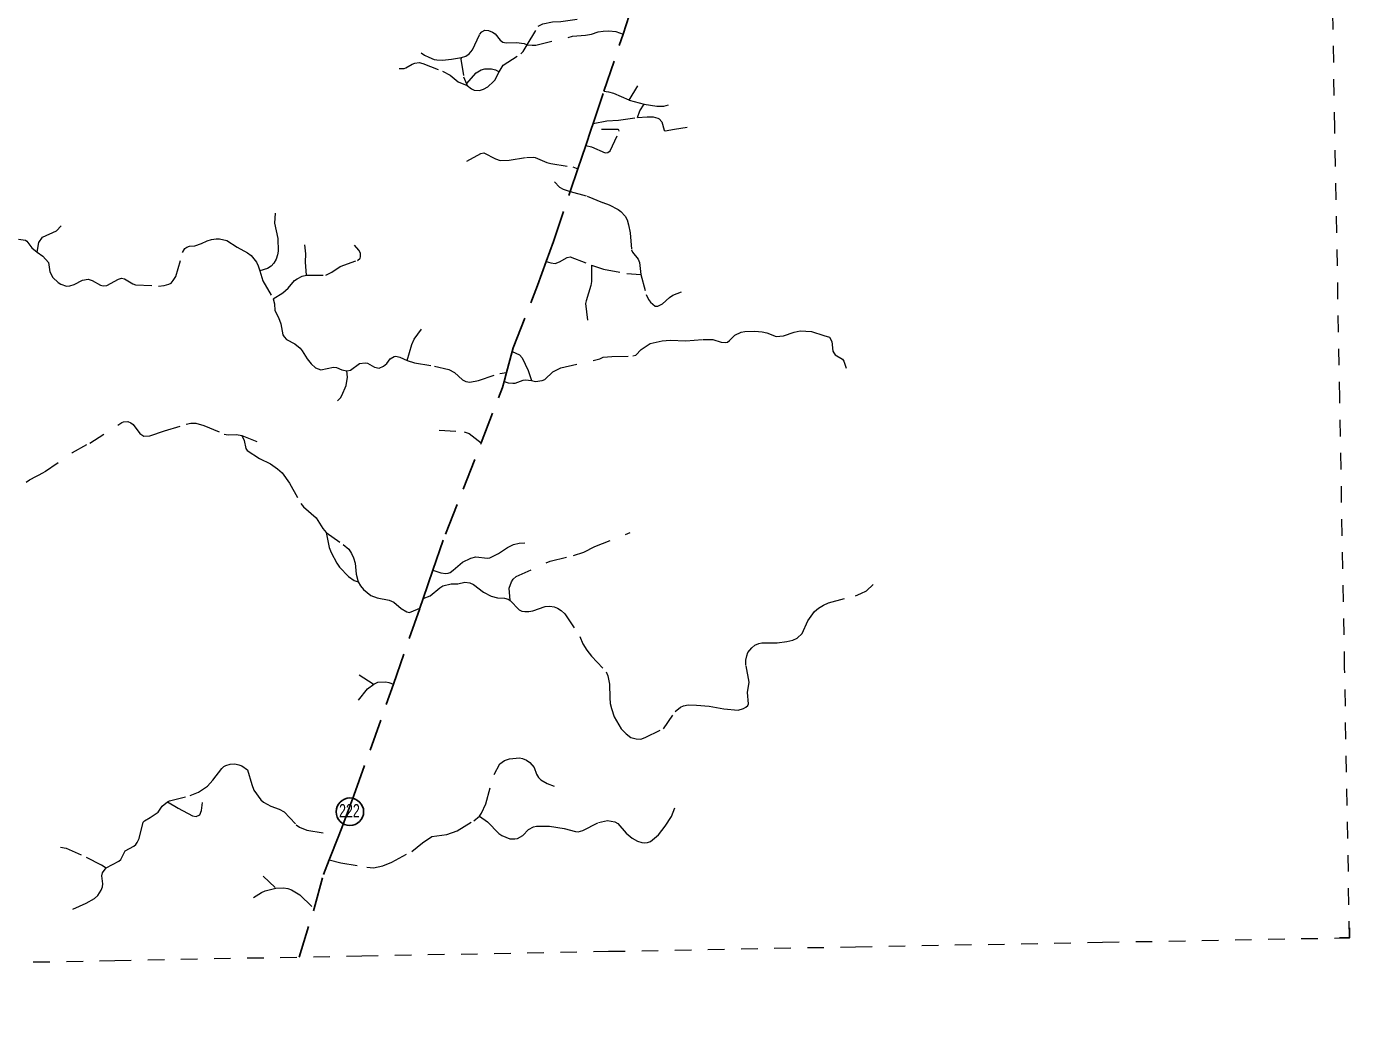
# Model space of a CAD drawing. Extents: x 220.8 to 246.7, y 7287.6 to 7315.8.
# Drawn here: x 238.66 to 246.65, y 7287.6 to 7293.59 of the extents above; entities that cross this region are included whole.
import ezdxf
from ezdxf.enums import TextEntityAlignment as Align

# ---------------------------------------------------------------- set-up
doc = ezdxf.new("R2010")
doc.units = 0
doc.header["$LTSCALE"] = 0.032
for name, pattern in [('DOTTED', [1.5, 0.3, -1.2]), ('LONG_DASHED', [7.5, 6, -1.5]), ('MEDIUM_DASHED', [4.5, 3, -1.5]), ('SHORT_DASHED', [2.7, 1.5, -1.2])]:
    doc.linetypes.add(name, pattern=pattern)
for name, color, linetype, lineweight in [('13', 7, 'Continuous', 25), ('35', 7, 'SHORT_DASHED', 13), ('4', 7, 'LONG_DASHED', 25), ('6', 7, 'MEDIUM_DASHED', 13), ('63', 7, 'Continuous', 25), ('7', 7, 'DOTTED', 13)]:
    doc.layers.add(name, color=color, linetype=linetype, lineweight=lineweight)
doc.layers.add('61', color=7, linetype='Continuous')

msp = doc.modelspace()

# ---------------------------------------------------------------- linework, layer by layer
at = {"layer": '13'}
msp.add_circle((240.6156, 7288.8468), 0.083, dxfattribs=at)
at = {"layer": '35'}
for points in [[(246.6507, 7288.0853), (246.6212, 7289.7146), (246.5917, 7291.3439), (246.5622, 7292.9732), (246.5328, 7294.6024), (246.5034, 7296.2317), (246.4739, 7297.861), (246.4446, 7299.4903), (246.4152, 7301.1196), (246.3858, 7302.7489), (246.3565, 7304.3782), (246.3272, 7306.0075), (246.2979, 7307.6367), (246.2685, 7309.266), (246.2393, 7310.8953), (246.21, 7312.5246), (246.1808, 7314.1539), (246.1516, 7315.7832)], [(221.3035, 7287.6034), (222.7945, 7287.633), (224.2855, 7287.6625), (225.7765, 7287.6918), (227.2675, 7287.7209), (228.7585, 7287.7499), (230.2495, 7287.7787), (231.7405, 7287.8074), (233.2315, 7287.836), (234.7225, 7287.8643), (236.2135, 7287.8925), (237.7045, 7287.9205), (239.1956, 7287.9483), (240.6866, 7287.9761), (242.1776, 7288.0036), (243.6686, 7288.031), (245.1597, 7288.0583), (246.6507, 7288.0853)]]:
    msp.add_lwpolyline(points, dxfattribs=at)
at = {"layer": '4'}
msp.add_lwpolyline([(240.3098, 7287.9691), (240.3989, 7288.2619), (240.4555, 7288.4673), (240.4904, 7288.5558), (240.5484, 7288.7025), (240.5735, 7288.766), (240.64, 7288.9443), (240.8785, 7289.6165), (241.0378, 7290.0769), (241.0582, 7290.1359), (241.1167, 7290.3055), (241.1922, 7290.5244), (241.409, 7291.0743), (241.5361, 7291.4105), (241.546, 7291.4468), (241.5606, 7291.4999), (241.5954, 7291.6273), (241.6014, 7291.649), (241.7482, 7292.0255), (241.8011, 7292.1711), (241.8449, 7292.2916), (241.9456, 7292.5928), (241.9918, 7292.7308), (242.0391, 7292.8714), (242.0721, 7292.9693), (242.084, 7293.0046), (242.1495, 7293.1993), (242.2645, 7293.5438), (242.3022, 7293.6576)], dxfattribs=at)
at = {"layer": '6'}
msp.add_line((239.9637, 7291.1189), (240.054, 7291.0825), dxfattribs=at)
for points in [[(241.7112, 7291.4509), (241.7368, 7291.4466), (241.776, 7291.452), (241.7921, 7291.4589), (241.8404, 7291.5034), (241.8887, 7291.5279), (242.125, 7291.5832), (242.1449, 7291.5924), (242.1963, 7291.5977), (242.3244, 7291.6), (242.3413, 7291.6039), (242.375, 7291.6384), (242.4279, 7291.6744), (242.5, 7291.6921), (242.5491, 7291.6951), (242.6442, 7291.6913), (242.7485, 7291.7005), (242.7884, 7291.7005), (242.8068, 7291.6997), (242.8575, 7291.6829), (242.8812, 7291.6821), (242.8943, 7291.6844), (242.9081, 7291.6944), (242.9403, 7291.7266), (242.9787, 7291.7442), (242.9994, 7291.7488), (243.0607, 7291.7504), (243.1052, 7291.745), (243.1336, 7291.7404), (243.1888, 7291.7182), (243.2341, 7291.7212), (243.2985, 7291.7442), (243.3338, 7291.7519), (243.4028, 7291.7488), (243.4772, 7291.7228), (243.5117, 7291.7143), (243.5255, 7291.6875), (243.5317, 7291.6299), (243.5363, 7291.6192), (243.5462, 7291.6062), (243.5892, 7291.5809), (243.5976, 7291.5694), (243.6122, 7291.5272)], [(241.5954, 7291.6273), (241.6386, 7291.6059), (241.6546, 7291.589), (241.6913, 7291.5127), (241.7112, 7291.4509)], [(241.546, 7291.4468), (241.5712, 7291.4382), (241.5988, 7291.4359), (241.6141, 7291.4367), (241.6609, 7291.4535), (241.6762, 7291.4551), (241.7112, 7291.4509)], [(238.6614, 7290.838), (238.6812, 7290.8522), (238.7716, 7290.9), (238.9406, 7291.0159), (239.0461, 7291.0742), (239.2382, 7291.1976), (239.2494, 7291.2014), (239.2741, 7291.2043), (239.2921, 7291.1969), (239.307, 7291.1857), (239.3481, 7291.1326), (239.3721, 7291.1146), (239.4072, 7291.1184), (239.4954, 7291.1483), (239.6263, 7291.1871), (239.6562, 7291.1939), (239.6861, 7291.1946), (239.7332, 7291.1797), (239.8566, 7291.1281), (239.8813, 7291.1243), (239.9306, 7291.1251), (239.9637, 7291.1189)], [(239.9637, 7291.1189), (239.9777, 7291.0899), (239.9874, 7291.0406), (239.9957, 7291.0286), (240.0704, 7290.9815), (240.1362, 7290.9494), (240.1788, 7290.9187), (240.2065, 7290.8933), (240.2506, 7290.832), (240.3194, 7290.7086), (240.3359, 7290.6884), (240.4114, 7290.6219), (240.4518, 7290.5568), (240.4727, 7290.5334), (240.5751, 7290.4619), (240.6095, 7290.432), (240.626, 7290.4073), (240.6379, 7290.3796), (240.6469, 7290.3475), (240.6529, 7290.2824), (240.6656, 7290.2361), (240.6798, 7290.2121), (240.6978, 7290.1897), (240.7426, 7290.1538), (240.7808, 7290.1396), (240.8518, 7290.1239), (240.881, 7290.1119), (240.9251, 7290.0753), (240.9602, 7290.0544), (240.9729, 7290.0506), (240.9856, 7290.0536), (241.0378, 7290.0769)], [(241.5825, 7290.1221), (241.5775, 7290.1972), (241.5903, 7290.2358), (241.6007, 7290.2526), (241.619, 7290.2669), (241.8253, 7290.3614), (241.9663, 7290.3946), (242.0281, 7290.4143), (242.0939, 7290.4499), (242.308, 7290.533)], [(241.0582, 7290.1359), (241.101, 7290.1517), (241.1587, 7290.2003), (241.1762, 7290.211), (241.2271, 7290.2231), (241.2666, 7290.2239), (241.3091, 7290.2338), (241.3395, 7290.23), (241.3608, 7290.2193), (241.4223, 7290.1722), (241.4678, 7290.1487), (241.5058, 7290.1388), (241.5499, 7290.1366), (241.5704, 7290.1305), (241.5825, 7290.1221)], [(241.5825, 7290.1221), (241.638, 7290.0674), (241.6539, 7290.0591), (241.6721, 7290.056), (241.6957, 7290.0568), (241.7192, 7290.0614), (241.7944, 7290.0864), (241.8225, 7290.0879), (241.8483, 7290.0841), (241.8696, 7290.0766), (241.8916, 7290.0629), (241.9137, 7290.0416), (242.004, 7289.9057), (242.0215, 7289.8601), (242.0458, 7289.8221), (242.0747, 7289.7864), (242.162, 7289.6923), (242.1719, 7289.6672), (242.1833, 7289.6171), (242.1848, 7289.535), (242.1878, 7289.5001), (242.1947, 7289.4713), (242.2106, 7289.4196), (242.2539, 7289.3467), (242.2828, 7289.3171), (242.3124, 7289.2943), (242.3443, 7289.2867), (242.3716, 7289.2859), (242.3982, 7289.2951), (242.5083, 7289.3482), (242.579, 7289.4523), (242.6109, 7289.4788), (242.6298, 7289.4864), (242.6572, 7289.4925), (242.7088, 7289.491), (242.7855, 7289.4849), (242.8729, 7289.4675), (242.9587, 7289.4606), (242.9921, 7289.4697), (243.0065, 7289.4781), (243.0172, 7289.4887), (243.0217, 7289.4994), (243.0157, 7289.5669), (243.0255, 7289.63), (243.0065, 7289.7318), (243.0065, 7289.7629), (243.0111, 7289.7887), (243.0187, 7289.8092), (243.0415, 7289.8373), (243.0597, 7289.8525), (243.0848, 7289.8639), (243.1022, 7289.8677), (243.1949, 7289.8677), (243.2541, 7289.8745), (243.2906, 7289.8836), (243.3149, 7289.8943), (243.346, 7289.9231), (243.3802, 7289.9998), (243.4212, 7290.056), (243.4448, 7290.0766), (243.4744, 7290.0955), (243.5048, 7290.1085), (243.6673, 7290.1517), (243.7007, 7290.1647), (243.7341, 7290.1821), (243.7744, 7290.2186)], [(238.9425, 7288.2584), (239.0241, 7288.2936), (239.0729, 7288.3221), (239.0934, 7288.3406), (239.1138, 7288.3728), (239.1218, 7288.3926), (239.1237, 7288.4117), (239.1181, 7288.46), (239.1224, 7288.4779), (239.1434, 7288.507), (239.2207, 7288.5478), (239.2331, 7288.5589), (239.2585, 7288.6102), (239.3104, 7288.6387), (239.3228, 7288.6498), (239.332, 7288.6609), (239.3432, 7288.6857), (239.3667, 7288.7828), (239.3753, 7288.7926), (239.4106, 7288.8112), (239.4582, 7288.844), (239.4823, 7288.8798), (239.5139, 7288.9062), (239.5268, 7288.9132), (239.6511, 7288.9442), (239.7018, 7288.9646), (239.755, 7289.0017), (239.7878, 7289.0369), (239.8422, 7289.1086), (239.8546, 7289.1192), (239.8657, 7289.126), (239.8929, 7289.1334), (239.9207, 7289.1358), (239.9455, 7289.1309), (239.964, 7289.1235), (239.9974, 7289.0994), (240.0234, 7289.0109), (240.0364, 7288.9775), (240.0778, 7288.9188), (240.0939, 7288.904), (240.1378, 7288.8811), (240.1891, 7288.8631), (240.2182, 7288.8458), (240.2918, 7288.7679), (240.3116, 7288.7531), (240.3555, 7288.7351), (240.5484, 7288.7025)]]:
    msp.add_lwpolyline(points, dxfattribs=at)
at = {"layer": '63'}
msp.add_lwpolyline([(246.5891, 7288.0853), (246.6507, 7288.0853), (246.6507, 7288.146)], dxfattribs=at)
at = {"layer": '7'}
for p, q in [((241.3196, 7293.2448), (241.3244, 7293.2344)), ((242.3024, 7293.1458), (242.3623, 7293.2479)), ((242.3024, 7293.1458), (242.3912, 7293.1203)), ((240.6712, 7289.6733), (240.7601, 7289.6177)), ((240.0913, 7288.4575), (240.1683, 7288.3858))]:
    msp.add_line(p, q, dxfattribs=at)
for points in [[(241.686, 7293.4803), (241.7526, 7293.5915), (241.7794, 7293.606), (241.8378, 7293.6188), (241.8887, 7293.6199), (242.1913, 7293.6681), (242.2523, 7293.6654), (242.3022, 7293.6576)], [(241.2884, 7293.4034), (241.3147, 7293.4111), (241.3357, 7293.4243), (241.3549, 7293.4494), (241.3977, 7293.5415), (241.4114, 7293.5584), (241.4292, 7293.5679), (241.4529, 7293.5661), (241.4757, 7293.557), (241.4917, 7293.5451), (241.5227, 7293.5073), (241.5386, 7293.4954), (241.5582, 7293.4922), (241.6216, 7293.4941), (241.6677, 7293.4868), (241.686, 7293.4803)], [(241.686, 7293.4803), (241.7151, 7293.4772), (241.7379, 7293.4786), (241.9604, 7293.531), (242.0375, 7293.5374), (242.0735, 7293.5447), (242.115, 7293.5579), (242.1442, 7293.5615), (242.1789, 7293.5634), (242.2213, 7293.5593), (242.2645, 7293.5438)], [(241.516, 7293.3172), (241.5411, 7293.3564), (241.6477, 7293.425), (241.6616, 7293.4394), (241.686, 7293.4803)], [(241.0453, 7293.4316), (241.0653, 7293.4179), (241.0927, 7293.4047), (241.1237, 7293.3919), (241.1401, 7293.3892), (241.1748, 7293.3878), (241.229, 7293.3928), (241.2884, 7293.4034)], [(241.2884, 7293.4034), (241.2863, 7293.393), (241.3017, 7293.2866), (241.3196, 7293.2448)], [(240.9123, 7293.3371), (240.9439, 7293.3371), (240.9536, 7293.3398), (240.9905, 7293.3628), (241.0076, 7293.3687), (241.0328, 7293.3725), (241.0553, 7293.3676), (241.1742, 7293.321), (241.2208, 7293.2964), (241.2695, 7293.2552), (241.3244, 7293.2344)], [(241.3196, 7293.2448), (241.3773, 7293.3106), (241.4077, 7293.3282), (241.4311, 7293.3343), (241.4705, 7293.3347), (241.4949, 7293.3292), (241.516, 7293.3172)], [(241.3244, 7293.2344), (241.3488, 7293.2139), (241.366, 7293.2064), (241.3986, 7293.2043), (241.4227, 7293.2123), (241.4474, 7293.2263), (241.4816, 7293.2573), (241.4897, 7293.267), (241.516, 7293.3172)], [(242.1495, 7293.1993), (242.1773, 7293.1963), (242.2075, 7293.1883), (242.3024, 7293.1458)], [(242.351, 7293.0403), (242.3656, 7293.08), (242.3912, 7293.1203)], [(242.3912, 7293.1203), (242.4678, 7293.1083), (242.5106, 7293.1091), (242.5387, 7293.1171)], [(242.084, 7293.0046), (242.1676, 7293.0202), (242.2377, 7293.0243), (242.351, 7293.0403)], [(242.351, 7293.0403), (242.41, 7293.0448), (242.4457, 7293.0443), (242.4745, 7293.0371), (242.4835, 7293.032), (242.4981, 7293.0137), (242.5123, 7292.9637), (242.5182, 7292.9593), (242.5752, 7292.9711), (242.6527, 7292.9814)], [(242.0391, 7292.8714), (242.0734, 7292.8636), (242.1561, 7292.8274), (242.1718, 7292.829), (242.1859, 7292.8399), (242.2414, 7292.9572), (242.2394, 7292.9665), (242.2346, 7292.9675), (242.0721, 7292.9693)], [(241.3208, 7292.776), (241.4057, 7292.8239), (241.4247, 7292.8264), (241.4949, 7292.7915), (241.523, 7292.7811), (241.5764, 7292.7832), (241.6809, 7292.7997), (241.7214, 7292.8014), (241.7333, 7292.7996), (241.8037, 7292.7688), (241.828, 7292.7621), (241.9619, 7292.7419), (241.9918, 7292.7308)], [(237.752, 7292.588), (237.7984, 7292.5956), (237.8896, 7292.598), (237.9549, 7292.588), (237.9832, 7292.5797), (238.0697, 7292.5439), (238.0903, 7292.5433), (238.1326, 7292.558), (238.1462, 7292.5586), (238.1673, 7292.5521), (238.2232, 7292.5221), (238.2621, 7292.5162), (238.2809, 7292.5068), (238.3021, 7292.4844), (238.3203, 7292.4403), (238.3391, 7292.4185), (238.3897, 7292.3991), (238.4727, 7292.3838), (238.5003, 7292.3732), (238.6145, 7292.3056), (238.6562, 7292.2997), (238.6651, 7292.2932), (238.6962, 7292.2538), (238.7275, 7292.2262)], [(241.8503, 7292.6522), (241.8819, 7292.6193), (241.9028, 7292.6082), (241.9456, 7292.5928), (242.0483, 7292.5664), (242.1417, 7292.5268), (242.1804, 7292.5135), (242.2356, 7292.485), (242.252, 7292.4725), (242.2769, 7292.4454), (242.2889, 7292.4223), (242.2983, 7292.3929), (242.3072, 7292.3444), (242.3152, 7292.2412), (242.3223, 7292.2274), (242.3557, 7292.1843), (242.3646, 7292.1638), (242.373, 7292.0914)], [(240.165, 7292.4629), (240.1594, 7292.4029), (240.1809, 7292.3093), (240.1823, 7292.2334), (240.1776, 7292.2114), (240.1701, 7292.1842), (240.1565, 7292.1603), (240.1406, 7292.1416), (240.1186, 7292.1275), (240.0716, 7292.1139)], [(238.7275, 7292.2262), (238.7381, 7292.285), (238.7595, 7292.3176), (238.8445, 7292.3555), (238.873, 7292.3862)], [(238.7275, 7292.2262), (238.761, 7292.2026), (238.7963, 7292.1644), (238.8039, 7292.1079), (238.8216, 7292.0744), (238.8551, 7292.0432), (238.871, 7292.0338), (238.9039, 7292.0226), (238.9245, 7292.0238), (238.9504, 7292.032), (239.0016, 7292.0585), (239.0351, 7292.0638), (239.0592, 7292.0567), (239.1098, 7292.0273), (239.1263, 7292.0232), (239.1487, 7292.0255), (239.2181, 7292.065), (239.2363, 7292.0691), (239.2552, 7292.0667), (239.3046, 7292.0349), (239.3205, 7292.0302), (239.4599, 7292.0226), (239.4946, 7292.0261), (239.5234, 7292.0344), (239.5364, 7292.0408), (239.5493, 7292.055), (239.5652, 7292.0803), (239.6058, 7292.2244), (239.6188, 7292.2485), (239.6317, 7292.2573), (239.647, 7292.2626), (239.6799, 7292.2662), (239.7188, 7292.2785), (239.7535, 7292.295), (239.7794, 7292.3032), (239.8088, 7292.3079), (239.8288, 7292.3079), (239.8735, 7292.2973), (239.9359, 7292.2573), (239.9976, 7292.2238), (240.0188, 7292.2067), (240.0512, 7292.1667), (240.0624, 7292.1444), (240.0716, 7292.1139)], [(240.3539, 7292.0872), (240.3475, 7292.1663), (240.3489, 7292.2163), (240.3431, 7292.2722)], [(240.3539, 7292.0872), (240.4701, 7292.0873), (240.5063, 7292.1064), (240.5568, 7292.1408), (240.6613, 7292.1775), (240.6773, 7292.191), (240.68, 7292.1984), (240.68, 7292.2216), (240.6699, 7292.2402), (240.6425, 7292.2703)], [(241.8011, 7292.1711), (241.8292, 7292.1617), (241.854, 7292.1588), (241.881, 7292.1686), (241.9269, 7292.1956), (241.9459, 7292.1985), (242.0737, 7292.1484)], [(240.0716, 7292.1139), (240.0906, 7292.0544), (240.1532, 7291.9452)], [(242.0737, 7292.1484), (242.0748, 7292.05), (242.07, 7292.0262), (242.041, 7291.9339), (242.0384, 7291.9161), (242.0536, 7291.7787)], [(242.0737, 7292.1484), (242.146, 7292.1253), (242.2871, 7292.099), (242.373, 7292.0914)], [(240.1532, 7291.9452), (240.2097, 7291.9809), (240.2421, 7292.0099), (240.2813, 7292.055), (240.2965, 7292.0658), (240.3264, 7292.0814), (240.3539, 7292.0872)], [(242.373, 7292.0914), (242.4041, 7291.9712), (242.4184, 7291.9405), (242.4308, 7291.9249), (242.4584, 7291.9014), (242.4753, 7291.9005), (242.5033, 7291.9156), (242.5447, 7291.9538), (242.5652, 7291.9667), (242.6177, 7291.9872)], [(240.1532, 7291.9452), (240.1594, 7291.9155), (240.163, 7291.8743), (240.1847, 7291.8326), (240.1988, 7291.795), (240.2106, 7291.7278), (240.2183, 7291.7149), (240.2336, 7291.6996), (240.283, 7291.6737), (240.3153, 7291.6472), (240.3283, 7291.6314), (240.3571, 7291.5825), (240.3818, 7291.5519), (240.4071, 7291.5278), (240.4395, 7291.5172), (240.5171, 7291.5331), (240.5354, 7291.5313), (240.5677, 7291.5172), (240.5964, 7291.5103)], [(240.9619, 7291.5724), (240.9902, 7291.669), (241.0043, 7291.7014), (241.0478, 7291.7625)], [(240.5964, 7291.5103), (240.6201, 7291.5143), (240.6731, 7291.5537), (240.7084, 7291.559), (240.7219, 7291.5572), (240.7631, 7291.5325), (240.7931, 7291.5272), (240.8178, 7291.5378), (240.839, 7291.5555), (240.8596, 7291.5831), (240.8825, 7291.5972), (240.8937, 7291.5984), (240.9166, 7291.5937), (240.9619, 7291.5724)], [(240.9619, 7291.5724), (241.006, 7291.5584), (241.1272, 7291.539), (241.2137, 7291.5178), (241.2461, 7291.5007), (241.2949, 7291.456), (241.3161, 7291.4454), (241.3285, 7291.4431), (241.3402, 7291.4425), (241.3914, 7291.4513), (241.5214, 7291.4949), (241.5606, 7291.4999)], [(240.5406, 7291.3294), (240.5589, 7291.3477), (240.5668, 7291.3603), (240.5921, 7291.4217), (240.6015, 7291.4718), (240.5964, 7291.5103)], [(241.1547, 7291.1515), (241.3062, 7291.1427), (241.3355, 7291.1309), (241.409, 7291.0743)], [(240.4727, 7290.5334), (240.491, 7290.4425), (240.502, 7290.4129), (240.5367, 7290.3492), (240.5528, 7290.3248), (240.6074, 7290.2688), (240.6409, 7290.2444), (240.6656, 7290.2361)], [(241.1167, 7290.3055), (241.1652, 7290.2891), (241.1944, 7290.2851), (241.2083, 7290.2881), (241.2201, 7290.2916), (241.2399, 7290.3059), (241.2959, 7290.3544), (241.3449, 7290.3777), (241.3755, 7290.3871), (241.4468, 7290.3782), (241.4612, 7290.3802), (241.5126, 7290.4064), (241.5661, 7290.4425), (241.6037, 7290.4608), (241.6374, 7290.4697), (241.672, 7290.4702)], [(240.6677, 7289.5205), (240.7225, 7289.5895), (240.7601, 7289.6177)], [(240.7601, 7289.6177), (240.784, 7289.6287), (240.8318, 7289.631), (240.8514, 7289.6279), (240.8785, 7289.6165)], [(241.3979, 7288.8206), (241.4099, 7288.8372), (241.4359, 7288.8949), (241.4858, 7289.0722), (241.5207, 7289.1355), (241.5486, 7289.1556), (241.5793, 7289.1663), (241.6389, 7289.1719), (241.657, 7289.1686), (241.6812, 7289.1584), (241.7013, 7289.1439), (241.7273, 7289.1141), (241.7427, 7289.0746), (241.7548, 7289.0532), (241.7678, 7289.0397), (241.8064, 7289.0173), (241.8479, 7289.0006)], [(239.5139, 7288.9062), (239.5786, 7288.8682), (239.6658, 7288.823), (239.6878, 7288.8175), (239.7093, 7288.8285), (239.7203, 7288.8533), (239.7253, 7288.9019)], [(241.3979, 7288.8206), (241.4465, 7288.7859), (241.5152, 7288.7159), (241.5322, 7288.7033), (241.5816, 7288.6835), (241.6105, 7288.6827), (241.6267, 7288.6855), (241.6599, 7288.7033), (241.6931, 7288.7385), (241.7247, 7288.7555), (241.7417, 7288.7602), (241.8196, 7288.7594), (241.9097, 7288.7452), (241.9773, 7288.7266), (241.9946, 7288.7246), (242.0227, 7288.7341), (242.1168, 7288.7812), (242.1717, 7288.7934), (242.216, 7288.7867), (242.233, 7288.776), (242.284, 7288.7167), (242.3195, 7288.6867), (242.3511, 7288.6689), (242.3772, 7288.661), (242.3918, 7288.6598), (242.4116, 7288.661), (242.4302, 7288.6677), (242.4792, 7288.7065), (242.5195, 7288.7602), (242.5574, 7288.8175), (242.5764, 7288.8713)], [(240.4904, 7288.5558), (240.56, 7288.5374), (240.7173, 7288.5114), (240.7573, 7288.5086), (240.8136, 7288.5193), (240.869, 7288.5412), (240.9886, 7288.6073), (241.0547, 7288.6589), (241.1097, 7288.6966), (241.2009, 7288.7097), (241.2633, 7288.7306), (241.3633, 7288.7925), (241.3979, 7288.8206)], [(238.8683, 7288.6325), (238.9017, 7288.6257), (239.0241, 7288.5725), (239.115, 7288.5255), (239.1434, 7288.507)], [(240.0342, 7288.3279), (240.0817, 7288.3597), (240.103, 7288.3693), (240.1683, 7288.3858)], [(240.1683, 7288.3858), (240.2148, 7288.3867), (240.2408, 7288.3837), (240.2631, 7288.3754), (240.3137, 7288.344), (240.3989, 7288.2619)]]:
    msp.add_lwpolyline(points, dxfattribs=at)

# ---------------------------------------------------------------- texts
at = {"layer": '61', "width": 0.7}
msp.add_text('222', height=0.08, dxfattribs=at).set_placement((240.6127, 7288.8128), align=Align.CENTER)

doc.saveas('drawing.dxf')
